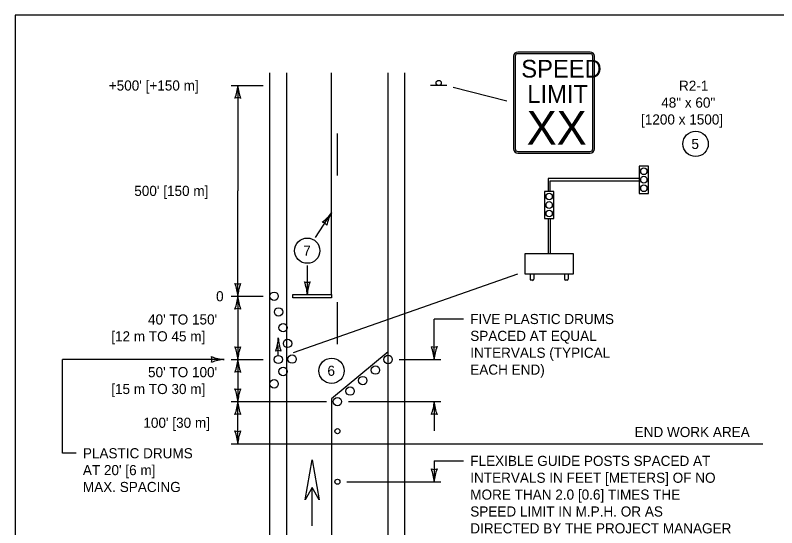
# Model space of a CAD drawing. Extents: x 49991.4 to 50021, y 49987.6 to 50011.4.
# Drawn here: x 50000.336 to 50004.847, y 50008.223 to 50011.263 of the extents above; entities that cross this region are included whole.
import ezdxf

# ---------------------------------------------------------------- set-up
doc = ezdxf.new("R2010")
doc.units = 0
for name, color, linetype in [('Level 1', 7, 'Continuous'), ('Level 2', 7, 'Continuous'), ('Level 3', 7, 'Continuous')]:
    doc.layers.add(name, color=color, linetype=linetype)

msp = doc.modelspace()

# ---------------------------------------------------------------- linework, layer by layer
at = {"layer": 'Level 1'}
for p, q in [((50003.2874, 50011.0196), (50003.2874, 50010.4696)), ((50003.2974, 50011.0196), (50003.2974, 50010.4696)), ((50003.7424, 50011.0446), (50003.3124, 50011.0446)), ((50003.7424, 50011.0346), (50003.3124, 50011.0346)), ((50003.7574, 50010.4696), (50003.7574, 50011.0196)), ((50003.7674, 50010.4696), (50003.7674, 50011.0196)), ((50001.8443, 50004.9471), (50001.8443, 50010.921)), ((50001.9443, 50004.9471), (50001.9443, 50010.921)), ((50002.2093, 50009.6059), (50002.2093, 50010.921)), ((50002.5443, 50004.9471), (50002.5443, 50010.921)), ((50002.6443, 50004.9471), (50002.6443, 50010.921)), ((50002.8923, 50010.846), (50002.7963, 50010.846)), ((50002.2443, 50010.3115), (50002.2443, 50010.5615)), ((50003.3124, 50010.4546), (50003.7424, 50010.4546)), ((50003.3124, 50010.4446), (50003.7424, 50010.4446)), ((50003.4921, 50010.2941), (50003.4921, 50010.2182)), ((50004.0318, 50010.2941), (50003.4921, 50010.2941)), ((50003.5048, 50010.2182), (50003.5048, 50010.2802)), ((50003.5048, 50010.2802), (50004.0318, 50010.2802)), ((50003.4921, 50010.0563), (50003.4921, 50009.847)), ((50003.5048, 50010.0563), (50003.5048, 50009.847)), ((50003.3859, 50009.7293), (50003.3859, 50009.6974)), ((50003.4071, 50009.7293), (50003.4071, 50009.6974)), ((50003.5898, 50009.7293), (50003.5898, 50009.6974)), ((50003.611, 50009.7293), (50003.611, 50009.6974)), ((50003.4008, 50009.6905), (50003.3923, 50009.6905)), ((50003.6047, 50009.6905), (50003.5962, 50009.6905)), ((50002.2443, 50009.3115), (50002.2443, 50009.5615)), ((50001.8943, 50009.245), (50001.8943, 50009.3033)), ((50002.5443, 50009.2666), (50002.2093, 50008.9873)), ((50002.2093, 50008.9873), (50002.2093, 50007.6045)), ((50002.0943, 50008.2351), (50002.0943, 50008.461)), ((50002.0946, 50008.2351), (50002.0946, 50008.461))]:
    msp.add_line(p, q, dxfattribs=at)
for points in [[(50008.6146, 50011.2628), (50000.3356, 50011.2628), (50000.3356, 50000.0624), (50008.6146, 50000.0624)], [(50004.0876, 50010.3681), (50004.0318, 50010.3681), (50004.0318, 50010.2063), (50004.0876, 50010.2063)], [(50003.5266, 50010.2182), (50003.4708, 50010.2182), (50003.4708, 50010.0563), (50003.5266, 50010.0563)], [(50003.6429, 50009.847), (50003.354, 50009.847), (50003.354, 50009.7293), (50003.6429, 50009.7293)], [(50001.9793, 50009.6059), (50002.2093, 50009.6059), (50002.2093, 50009.5859), (50001.9793, 50009.5859)], [(50002.0526, 50008.3887), (50002.0943, 50008.6252), (50002.1362, 50008.3887), (50002.0943, 50008.4609)]]:
    msp.add_lwpolyline(points, close=True, dxfattribs=at)
for centre, radius in [((50002.8443, 50010.8612), 0.0152), ((50001.8693, 50009.596), 0.025), ((50001.8959, 50009.5028), 0.025), ((50001.9225, 50009.4097), 0.025), ((50001.9491, 50009.3166), 0.025), ((50001.8943, 50009.221), 0.024), ((50001.9756, 50009.2235), 0.025), ((50002.5443, 50009.221), 0.025), ((50001.9225, 50009.15), 0.025), ((50002.4693, 50009.1585), 0.025), ((50002.3943, 50009.096), 0.025), ((50001.8693, 50009.0764), 0.025), ((50002.3193, 50009.0335), 0.025), ((50002.2443, 50008.971), 0.025), ((50002.2443, 50008.7958), 0.015), ((50002.2443, 50008.4958), 0.015)]:
    msp.add_circle(centre, radius, dxfattribs=at)
for centre, radius, start, end in [((50003.3124, 50011.0196), 0.025, 90, 180), ((50003.3124, 50011.0196), 0.015, 90, 180), ((50003.7424, 50011.0196), 0.025, 0, 90), ((50003.7424, 50011.0196), 0.015, 0, 90), ((50003.3124, 50010.4696), 0.025, 180, 270), ((50003.3124, 50010.4696), 0.015, 180, 270), ((50003.7424, 50010.4696), 0.025, 270, 0), ((50003.7424, 50010.4696), 0.015, 270, 0)]:
    msp.add_arc(centre, radius, start, end, dxfattribs=at)
for centre in [(50004.0597, 50010.3377), (50004.0597, 50010.2872), (50004.0597, 50010.2366), (50003.4987, 50010.1878), (50003.4987, 50010.1372), (50003.4987, 50010.0867)]:
    msp.add_ellipse(centre, major_axis=(0, -0.0202), ratio=0.91873, dxfattribs=at)
for centre, major_axis, ratio, start_param, end_param in [((50003.3923, 50009.6974), (0, 0.00693), 0.91873, 1.570718, 3.141895), ((50003.4008, 50009.6974), (0, 0.00693), 0.91873, 3.140989, 4.712467), ((50003.5962, 50009.6974), (0, 0.00694), 0.91873, 1.570784, 3.141406), ((50003.6047, 50009.6974), (0, 0.00694), 0.91873, 3.141593, 4.712389), ((50001.6889, 50009.3579), (0, 0.2263), 0.908162, 4.318922, 4.671191), ((50002.1094, 50009.3603), (0, -0.2372), 0.908162, 4.761735, 5.097708), ((50001.8943, 50009.218), (0, 0.0558), 0.908162, 5.971449, 6.594922)]:
    msp.add_ellipse(centre, major_axis=major_axis, ratio=ratio, start_param=start_param, end_param=end_param, dxfattribs=at)
at = {"layer": 'Level 2'}
for centre in [(50004.3665, 50010.4996), (50002.0657, 50009.8663), (50002.2098, 50009.1542)]:
    msp.add_circle(centre, 0.075, dxfattribs=at)
at = {"layer": 'Level 3'}
for p, q in [((50001.6143, 50010.846), (50001.8043, 50010.846)), ((50001.6543, 50010.846), (50001.6543, 50010.221)), ((50002.931, 50010.836), (50003.2487, 50010.7545)), ((50001.6543, 50009.596), (50001.6543, 50010.221)), ((50002.1142, 50009.9452), (50002.2093, 50010.0902)), ((50002.0657, 50009.7793), (50002.0657, 50009.6059)), ((50001.6143, 50009.596), (50001.8043, 50009.596)), ((50001.6543, 50009.596), (50001.6543, 50009.221)), ((50002.9914, 50009.4611), (50002.8178, 50009.4611)), ((50002.8178, 50009.221), (50002.8178, 50009.4611)), ((50001.5743, 50009.221), (50000.6164, 50009.221)), ((50000.6164, 50008.665), (50000.6164, 50009.221)), ((50001.6143, 50009.221), (50001.8043, 50009.221)), ((50001.6543, 50009.221), (50001.6543, 50008.971)), ((50002.6093, 50009.221), (50002.8578, 50009.221)), ((50001.6143, 50008.971), (50002.1793, 50008.971)), ((50001.6543, 50008.7209), (50001.6543, 50008.971)), ((50002.3093, 50008.971), (50002.8578, 50008.971)), ((50002.8178, 50008.971), (50002.8178, 50008.7976)), ((50001.6143, 50008.7209), (50004.7645, 50008.7209)), ((50000.6964, 50008.665), (50000.6164, 50008.665)), ((50002.8178, 50008.6197), (50002.9914, 50008.6197)), ((50002.8178, 50008.6197), (50002.8178, 50008.4958)), ((50002.2993, 50008.4958), (50002.8578, 50008.4958))]:
    msp.add_line(p, q, dxfattribs=at)
msp.add_lwpolyline([(50001.9843, 50009.2619), (50003.314, 50009.7293)], dxfattribs=at)
for centre, radius, start, end in [((50001.4322, 50010.8551), 0.2223, 337.456, 357.6395), ((50001.887, 50010.8574), 0.233, 182.8273, 202.0772), ((50001.6543, 50010.7177), 0.0548, 72.1388, 107.8612), ((50002.0286, 50010.2197), 0.2223, 304.1865, 324.37), ((50002.4102, 50009.9721), 0.233, 149.5578, 168.8076), ((50002.139, 50009.983), 0.0548, 38.8693, 74.5916), ((50001.6543, 50009.7242), 0.0548, 252.1388, 287.8612), ((50001.4216, 50009.5845), 0.233, 2.8273, 22.0772), ((50001.8764, 50009.5868), 0.2223, 157.456, 177.6395), ((50002.0657, 50009.7342), 0.0548, 252.1388, 287.8612), ((50001.833, 50009.5945), 0.233, 2.8273, 22.0772), ((50002.2878, 50009.5968), 0.2223, 157.456, 177.6395), ((50001.4322, 50009.6051), 0.2223, 337.456, 357.6395), ((50001.887, 50009.6074), 0.233, 182.8273, 202.0772), ((50001.6543, 50009.4677), 0.0548, 72.1388, 107.8612), ((50001.6543, 50009.3492), 0.0548, 252.1388, 287.8612), ((50001.4216, 50009.2095), 0.233, 2.8273, 22.0772), ((50001.8764, 50009.2118), 0.2223, 157.456, 177.6395), ((50002.8178, 50009.3493), 0.0548, 252.1388, 287.8612), ((50002.5851, 50009.2095), 0.233, 2.8273, 22.0772), ((50003.0399, 50009.2119), 0.2223, 157.456, 177.6395), ((50001.5835, 50009.4431), 0.2223, 247.456, 267.6395), ((50001.4461, 50009.221), 0.0548, 342.1388, 17.8612), ((50001.5858, 50008.9882), 0.233, 92.8273, 112.0772), ((50001.4322, 50009.2301), 0.2223, 337.456, 357.6395), ((50001.887, 50009.2324), 0.233, 182.8273, 202.0772), ((50001.6543, 50009.0927), 0.0548, 72.1388, 107.8612), ((50001.6543, 50009.0992), 0.0548, 252.1388, 287.8612), ((50001.4216, 50008.9595), 0.233, 2.8273, 22.0772), ((50001.8764, 50008.9618), 0.2223, 157.456, 177.6395), ((50001.4322, 50008.9801), 0.2223, 337.456, 357.6395), ((50001.887, 50008.9824), 0.233, 182.8273, 202.0772), ((50002.5957, 50008.9801), 0.2223, 337.456, 357.6395), ((50003.0505, 50008.9824), 0.233, 182.8273, 202.0772), ((50001.6543, 50008.8427), 0.0548, 72.1388, 107.8612), ((50002.8178, 50008.8427), 0.0548, 72.1388, 107.8612), ((50001.6543, 50008.8491), 0.0548, 252.1388, 287.8612), ((50001.4216, 50008.7094), 0.233, 2.8273, 22.0772), ((50001.8764, 50008.7117), 0.2223, 157.456, 177.6395), ((50002.8178, 50008.624), 0.0548, 252.1388, 287.8612), ((50002.5851, 50008.4843), 0.233, 2.8273, 22.0772), ((50003.0399, 50008.4866), 0.2223, 157.456, 177.6395)]:
    msp.add_arc(centre, radius, start, end, dxfattribs=at)

# ---------------------------------------------------------------- texts
at = {"layer": 'Level 1'}
for s, height, p in [('SPEED', 0.10512, (50003.3336, 50010.893)), ('LIMIT', 0.10512, (50003.3691, 50010.7429)), ('XX', 0.19892, (50003.3659, 50010.4956))]:
    msp.add_text(s, height=height, dxfattribs=at).set_placement(p)
at = {"layer": 'Level 2'}
for s, p in [("+500' [+150 m]", (50000.8897, 50010.816)), ('R2-1', (50004.2682, 50010.8146)), ('48" x 60"', (50004.1627, 50010.7146)), ('[1200 x 1500]', (50004.0432, 50010.6146)), ('5', (50004.3416, 50010.4696)), ("500' [150 m]", (50001.0409, 50010.191)), ('7', (50002.0419, 50009.8363)), ('0', (50001.5255, 50009.566)), ("40' TO 150'", (50001.1223, 50009.4285)), ('FIVE PLASTIC DRUMS', (50003.0314, 50009.4311)), ('[12 m TO 45 m]', (50000.9043, 50009.3285)), ('SPACED AT EQUAL', (50003.0314, 50009.3311)), ('INTERVALS (TYPICAL', (50003.0314, 50009.2311)), ("50' TO 100'", (50001.1223, 50009.116)), ('6', (50002.1852, 50009.1242)), ('EACH END)', (50003.0314, 50009.1311)), ('[15 m TO 30 m]', (50000.9043, 50009.016)), ("100' [30 m]", (50001.0948, 50008.8159)), ('END WORK AREA', (50004.0053, 50008.7609)), ('PLASTIC DRUMS ', (50000.7364, 50008.635)), ('FLEXIBLE GUIDE POSTS SPACED AT  ', (50003.0314, 50008.5897)), ("AT 20' [6 m] ", (50000.7364, 50008.535)), ('INTERVALS IN FEET [METERS] OF NO ', (50003.0314, 50008.4897)), ('MAX. SPACING', (50000.7364, 50008.435)), ('MORE THAN 2.0 [0.6] TIMES THE ', (50003.0314, 50008.3897)), ('SPEED LIMIT IN M.P.H. OR AS ', (50003.0314, 50008.2897)), ('DIRECTED BY THE PROJECT MANAGER ', (50003.0314, 50008.1897))]:
    msp.add_text(s, height=0.06, dxfattribs=at).set_placement(p)

doc.saveas('drawing.dxf')
